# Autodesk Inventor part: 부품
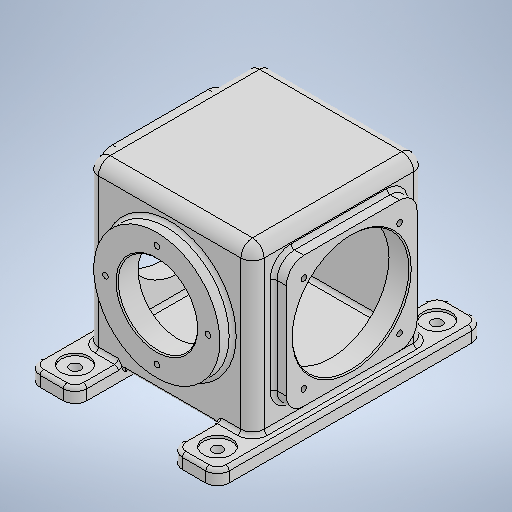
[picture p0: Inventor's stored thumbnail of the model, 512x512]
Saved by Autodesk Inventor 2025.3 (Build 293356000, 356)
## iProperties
Created: 2026-01
Part Number: 부품
Material: 일반
Document SubType Name: Modeling
Designer: pc6
Density: 1 g/cm^3
Appearance: 기본값
Author: pc6
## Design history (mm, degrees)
sketch "스케치1"
  geometry: L1 (71, -72)-(-71, -72); L2 (-71, -72)-(-71, 72); L3 (-71, 72)-(71, 72); L4 (71, 72)-(71, -72); 3 further points
  constraints: 8 end point, 2 midpoint, 2 parallel, 1 horizontal, 1 horizontal alignment, 1 perpendicular, 1 vertical alignment
  dimensions: "d0" = 142 distance between parallel lines of L4 L2; "d1" = 144 distance between parallel lines of L1 L3
extrude "돌출1" new body sketch "스케치1" stored distance "d2" = 148; taper "d3" = 0 deg
sketch "스케치2"
  geometry: L1 (-10, 40)-(30, 40); L2 (30, 40)-(30, -188); L3 (30, -188)-(-10, -188); L4 (-10, -188)-(-10, 40); L5 (112, 40)-(152, 40); L6 (152, 40)-(152, -188); L7 (152, -188)-(112, -188); L8 (112, -188)-(112, 40); 5 further points
  constraints: 16 end point, 4 midpoint, 4 parallel, 2 horizontal, 2 horizontal alignment, 2 perpendicular
  dimensions: "d4" = 40 distance of L2.end L3.end; "d5" = 228 distance between parallel lines of L3 L1; "d6" = 40 distance of L6.end L7.end; "d7" = 228 distance between parallel lines of L7 L5; "d8" = 162 distance from line of point (152, -74) L4; "d9" = 81 distance of point (71, -74) point (-10, -74)
feature "쉘1" dims "d10" = 7
extrude "돌출2" join sketch "스케치2" distance "d11" = 8; taper "d12" = 0 deg; dims "d89" = 4, "d90" = 0
sketch "스케치5"
  geometry: L1 (130, -126)-(18, -126); L2 (18, -126)-(18, -14); L3 (18, -14)-(130, -14); L4 (130, -14)-(130, -126); L5 (130, -126)-(18, -14); L6 (18, -126)-(130, -14); L7 (188, -152)-(-40, -152) reference; 2 further points
  constraints: 12 end point, 2 midpoint, 2 parallel, 1 horizontal, 1 perpendicular, 1 vertical alignment
  dimensions: "d19" = 112 distance of L2.end L3.end; "d20" = 112 distance of L1.end L2.end; "d21" = 82 distance from line of L7 point (74, -70)
extrude "돌출5" join sketch "스케치5" distance "d22" = 11; taper "d23" = 0 deg
sketch "스케치6"
  geometry: L1 (188, -152)-(-40, -152) reference; C1 r 50 at (74, -70); 1 further point
  constraints: 1 centre point, 1 vertical alignment
  dimensions: "d24" = 100 diameter of C1; "d25" = 82 distance from line of L1 C1.centre
extrude "돌출6" cut sketch "스케치6" stored distance "d26" = 13; taper "d27" = 0 deg
sketch "스케치7"
  geometry: L1 (81, -80)-(41, -80) reference; C1 r 54 at (0, 2); C2 r 34 at (0, 2); 1 further point
  constraints: 2 centre point, 1 coincident, 1 vertical alignment
  dimensions: "d28" = 108 diameter of C1; "d29" = 82 distance from line of L1 C1.centre; "d30" = 68 diameter of C2
extrude "돌출7" join sketch "스케치7" distance "d31" = 11; taper "d32" = 0 deg
sketch "스케치8"
  geometry: L1 (81, -82)-(41, -82) reference; C1 r 34 at (0, 0); 2 further points
  constraints: 1 centre point, 1 midpoint, 1 vertical alignment
  dimensions: "d33" = 68 diameter of C1; "d34" = 82 vertical distance of point (61, -82) C1.centre
extrude "돌출8" cut sketch "스케치8" stored distance "d35" = 11; taper "d36" = 0 deg
sketch "스케치9"
  geometry: 5 further points
  constraints: 1 horizontal alignment
  dimensions: "d44" = 82 distance of point (115, -31) point (33, -31); "d45" = 82 distance of point (33, -113) point (33, -31); "d46" = 82 distance of point (33, -113) point (115, -113); "d47" = 82 distance of point (115, -113) point (115, -31); "d48" = 41 horizontal distance of point (74, -72) point (33, -31); "d49" = 41 horizontal distance of point (115, -113) point (74, -72)
hole "구멍1" sketch "스케치9" at (115, -31), (33, -31), (33, -113), (115, -113) diameter "d37" = 4.917; stored, may be unused: countersink angle "d41" = 90 deg, drill point angle "d43" = 118 deg; dims "d38" = 12, "d39" = 4, "d40" = 2, "d42" = 12
sketch "스케치10" dims "d57" = 88
  geometry: L1 (81, -82)-(41, -82) reference; 4 further points
  constraints: 3 vertical alignment, 1 midpoint, 2 other
  dimensions: "d58" = 82 vertical distance of point (61, -82) point (0, 0)
hole "구멍2" sketch "스케치10" at (0, 44) diameter "d50" = 4.917; stored, may be unused: countersink angle "d54" = 90 deg, drill point angle "d56" = 118 deg; dims "d51" = 12, "d52" = 4, "d53" = 2, "d55" = 12
fillet "모깎기1" dims "d62" = 10
fillet "모깎기2" dims "d63" = 10
fillet "모깎기5" dims "d66" = 15
fillet "모깎기6" dims "d67" = 3
chamfer "모따기1" distance "d68" = 1; stored, may be unused: second distance "d69" = 2, angle "d70" = 45 deg
fillet "모깎기7" dims "d71" = 3
sketch "스케치11"
  geometry: C1 r 12 at (10, -20); C2 r 12 at (132, -20); C3 r 12 at (132, 168); C4 r 12 at (10, 168); C5 r 4.5 at (10, -20); C6 r 4.5 at (132, -20); C7 r 4.5 at (132, 168); C8 r 4.5 at (10, 168); 1 further point
  constraints: 8 centre point, 4 coincident, 2 horizontal alignment, 1 vertical alignment
  dimensions: "d72" = 24 diameter of C1; "d73" = 24 diameter of C2; "d74" = 24 diameter of C3; "d75" = 24 diameter of C4; "d76" = 188 distance of C2.centre C3.centre; "d77" = 188 distance of C1.centre C4.centre; "d78" = 122 distance of C4.centre C3.centre; "d79" = 61 horizontal distance of C2.centre point (71, 74); "d80" = 94 vertical distance of C2.centre point (71, 74); "d83" = 9 diameter of C5; "d84" = 9 diameter of C6; "d85" = 9 diameter of C7; "d86" = 9 diameter of C8
extrude "돌출9" cut sketch "스케치11" distance "d81" = 2; taper "d82" = 0 deg
extrude "돌출10" cut sketch "스케치11" extent not by distance; stored distance "d87" = 0; taper "d88" = 0 deg
fillet "모깎기8" dims "d91" = 3
feature "˄耀ˆ耀ˈ耀ˊ耀ˌ耀ˎ耀ː耀˒耀" dims "d0" = 142, "d1" = 144, "d2" = 148, "d3" = 0, "d4" = 40, "d5" = 228, "d6" = 40, "d7" = 228, "d8" = 162, "d9" = 81, "d10" = 7, "d11" = 8, "d12" = 0, "d19" = 112, "d20" = 112, "d21" = 82, "d22" = 11, "d23" = 0, "d24" = 100, "d25" = 82, "d26" = 13, "d27" = 0, "d28" = 108, "d29" = 82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
node "솔리드1"
mirror "미러1"
pattern_circular "원형 패턴1" dims angle "d60" = 360 deg
node "작업 평면1"
feature "A9D066F2-1C7D-4E18-AEED-F7BC21143FA4" dims "d37" = 4.917, "d38" = 12, "d39" = 4, "d40" = 2, "d41" = 90 deg, "d42" = 12, "d43" = 118 deg
